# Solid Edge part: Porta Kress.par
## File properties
Author: f_grande
Template: Normal.par
Last saved by: f_grande
Revision: 3
Application: Solid Edge
Material: Alluminio, 1060
Stile della faccia: Alluminio
Stile di riempimento: ANSI38(Alluminio)
Stile virtuale: Alluminio lucidato
Coef. of Thermal Exp: 0.0
Thermal Conductivity: 221.0
Specific Heat: 920.0
Modulus of Elasticity: 68947570000.0
Poisson's Ratio: 0.33
Yield Stress: 27579028.0
Ultimate Stress: 68947570.0
Elongation: 0.0
Tipo di contenuto documento: 0
Densità: 2712,000 kg/m^3
Precisione: 0,990
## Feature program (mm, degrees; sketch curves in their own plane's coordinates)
sketch for "unnamed Protrusion 1" plane through (0, 0, 0) normal (0, -1, 0) x-axis (1, 0, 0)
  line (-42.5, 72.5) -> (42.5, 72.5)
  line (42.5, 72.5) -> (42.5, -72.5)
  line (42.5, -72.5) -> (-42.5, -72.5)
  line (-42.5, -72.5) -> (-42.5, 72.5)
  dimension (linear) = 42.5
  dimension (linear) = 42.5
extrude "unnamed Protrusion 1" add finite 15 along +normal
sketch for "Foro_1" plane through (0, -15, 0) normal (0, -1, 0) x-axis (1, 0, 0)
  hole centre (25, 58.9984) bore radius 3
hole "Foro_1" diameter 6 through
sketch for "unnamed Hole 1" plane through (0, -15, 0) normal (0, -1, 0) x-axis (1, 0, 0)
  hole centre (-25, 58.9984) bore radius 3
hole "unnamed Hole 1" through
pattern "unnamed Pattern 1" of "Foro_1", "unnamed Hole 1"
chamfer "Smusso_1" setback 1
sketch for "ExtrudedProtrusion_2" plane through (0, -15, 0) normal (0, -1, 0) x-axis (1, 0, 0)
  line (-42.5, -72.5) -> (42.5, -72.5)
  line (42.5, -72.5) -> (42.5, -52.5)
  line (42.5, -52.5) -> (-42.5, -52.5)
  line (-42.5, -52.5) -> (-42.5, -72.5)
  dimension (linear) = 42.5
extrude "ExtrudedProtrusion_2" add finite 65 along +normal
sketch for "ExtrudedCutout_1" plane through (0, -47.5, -52.5) normal (0, 0, 1) x-axis (1, 0, 0)
  line (1, -22.4769) -> (1, -32.5)
  line (1, -32.5) -> (-1, -32.5)
  line (-1, -32.5) -> (-1, -22.4769)
  dimension (linear) = 1
extrude "ExtrudedCutout_1" cut finite 40.0861 along -normal
sketch for "Foro_3" plane through (-42.5, -40, 0) normal (-1, 0, 0) x-axis (0, -1, 0)
  hole centre (35, -62.5) bore radius 2.1
hole "Foro_3" nominal diameter 5 through  ThreadDepth = 2 mm
sketch for "ExtrudedCutout_2" plane through (-42.5, -40, 0) normal (-1, 0, 0) x-axis (0, -1, 0)
  circle centre (35, -62.5) radius 4
extrude "ExtrudedCutout_2" cut finite 8 along -normal
chamfer "Smusso_2" setback 0.5
sketch for "ExtrudedCutout_3" plane through (0, -47.5, -52.5) normal (0, 0, 1) x-axis (0, -1, 0)
  line (-32.5, -42.5) -> (-32.5, -42)
  line (-32, -42.5) -> (-32.5, -42)
  line (-32.5, -42.5) -> (-32, -42.5)
extrude "ExtrudedCutout_3" cut finite 33.4958 along -normal
sketch for "ExtrudedCutout_4" plane through (0, -47.5, -52.5) normal (0, 0, 1) x-axis (0, -1, 0)
  line (-32.5, 42.5) -> (-32.5, 42)
  line (-32, 42.5) -> (-32.5, 42)
  line (-32.5, 42.5) -> (-32, 42.5)
extrude "ExtrudedCutout_4" cut finite 95.1327 along -normal
sketch for "ExtrudedCutout_5" plane through (-42.5, -47.75, -62.5) normal (-1, 0, 0) x-axis (0, 1, 0)
  line (32.75, 10) -> (32.25, 10)
  line (32.75, 10) -> (32.75, 9.5)
  line (32.75, 9.5) -> (32.25, 10)
extrude "ExtrudedCutout_5" cut finite 109.2858 along -normal
sketch for "ExtrudedCutout_6" plane through (-42.5, -47.75, -62.5) normal (-1, 0, 0) x-axis (0, -1, 0)
  line (-32.25, 10) -> (-32.75, 10)
  line (-32.75, 10) -> (-32.75, 9.5)
  line (-32.75, 9.5) -> (-32.25, 10)
extrude "ExtrudedCutout_6" cut finite 124.1408 along -normal
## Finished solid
Body 1: solid body, 28 faces, 57 edges, 28 vertices.
  Faces by surface: plane 19, cylinder 6, cone 3
  Edges by curve: line 42, circle 15
Bounding box of the edges (mm): 85.000 x 80.000 x 145.000, from (-42.5, -80, -72.5) to (42.5, 0, 72.5).
Cylindrical faces by radius (mm): R2.1 x2, R3 x2, R4 x1, R21.6 x1
Conical faces (half-angle, radius in mm at the cone's reference point): 45 deg R4 x2, 45 deg R4.5 x1
Planar faces by outward normal: +x 3, +y 1, +z 2, -x 4, -y 3, -z 2, oblique 4
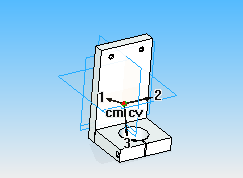
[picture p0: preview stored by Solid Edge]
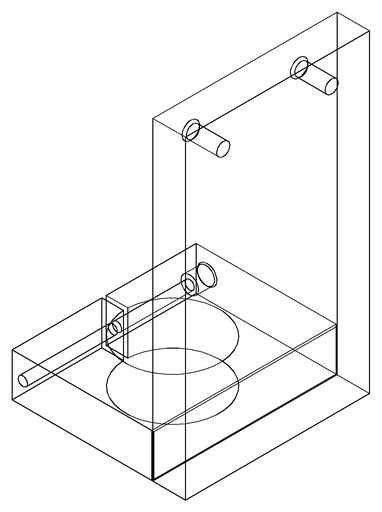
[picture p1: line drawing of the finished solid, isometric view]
